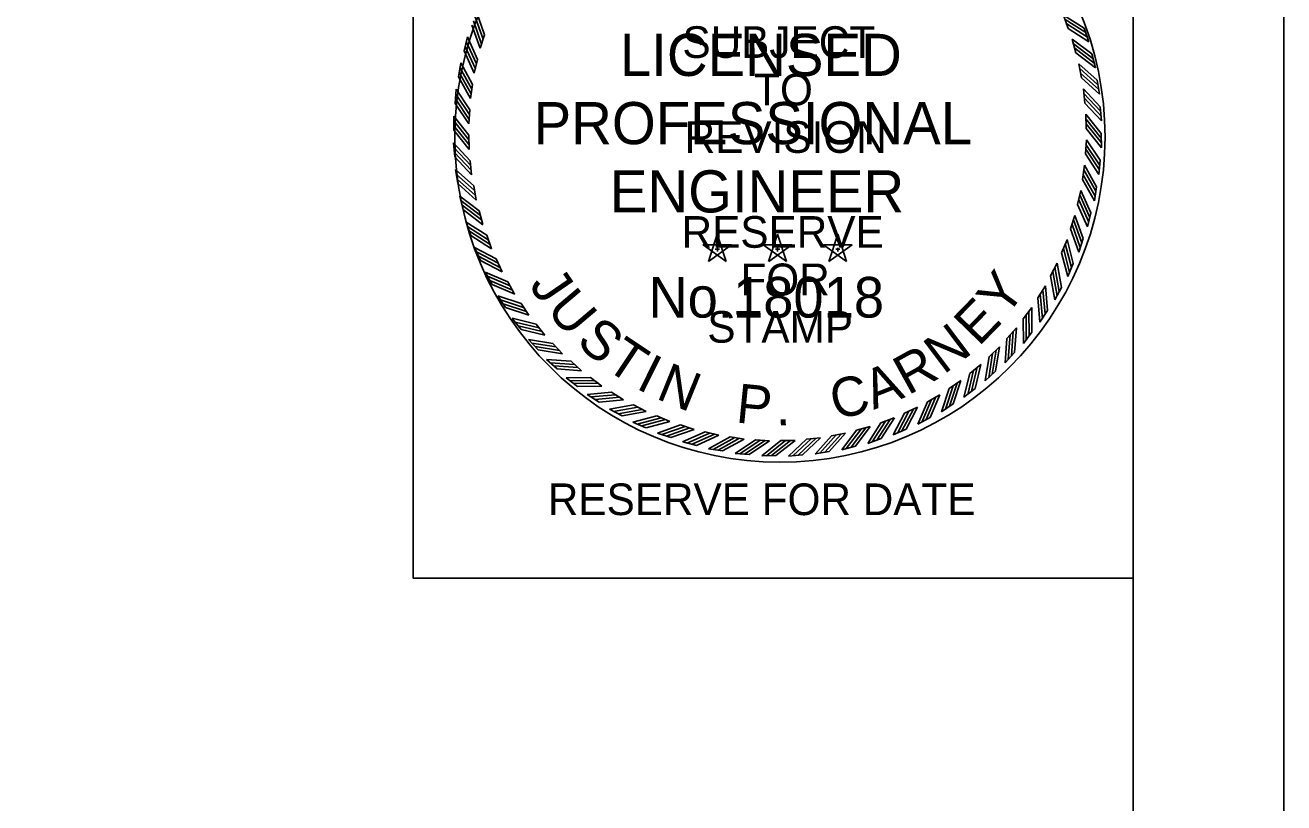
# Model space of a CAD drawing. Extents: x 0 to 1228743, y 0 to 152440.
# Drawn here: x 29.181 to 34, y 16.545 to 19.522 of the extents above; entities that cross this region are included whole.
import ezdxf

# ---------------------------------------------------------------- set-up
doc = ezdxf.new("R2010")
doc.units = 0
for name, color, linetype in [('R_Border', 7, 'Continuous'), ('R_Draft', 7, 'Continuous'), ('R_No Plot', 7, 'Continuous'), ('STAMP_JUSTIN', 7, 'Continuous')]:
    doc.layers.add(name, color=color, linetype=linetype)

msp = doc.modelspace()

# ---------------------------------------------------------------- linework, layer by layer
at = {"layer": 'R_Border'}
msp.add_line((33.4232, 0.5768), (33.4232, 21.4232), dxfattribs=at)
msp.add_lwpolyline([(34, 22), (0, 22), (0, 0), (34, 0)], close=True, dxfattribs=at)
at = {"layer": 'R_Draft'}
msp.add_circle((32.0709, 19.0937), 1.2447, dxfattribs=at)
at = {"layer": 'R_No Plot'}
for points in [[(33.4232, 17.4053), (33.4232, 10.8708), (1.516, 10.8708), (1.516, 21.4232), (27.1592, 21.4232), (27.1592, 20.4352), (28.7492, 20.4352), (30.6666, 20.4352)], [(30.6666, 20.4352), (30.6666, 17.4053), (33.4232, 17.4053)]]:
    msp.add_lwpolyline(points, dxfattribs=at)
at = {"layer": 'STAMP_JUSTIN'}
for p, q in [((33.1567, 19.5604), (33.1749, 19.5091)), ((30.8619, 19.4237), (30.8748, 19.4765)), ((30.9231, 19.4331), (30.9403, 19.4848)), ((33.1899, 19.4685), (33.2038, 19.4158)), ((33.236, 19.5098), (33.2541, 19.4586)), ((30.8404, 19.3236), (30.8488, 19.3773)), ((30.9006, 19.338), (30.9135, 19.3909)), ((33.2154, 19.3741), (33.2248, 19.3205)), ((33.2647, 19.4115), (33.2785, 19.3589)), ((30.8272, 19.222), (30.8312, 19.2762)), ((30.886, 19.2413), (30.8945, 19.2952)), ((33.233, 19.2779), (33.238, 19.2237)), ((33.2852, 19.3111), (33.2946, 19.2576)), ((30.8794, 19.1438), (30.8834, 19.1981)), ((33.2426, 19.1807), (33.2431, 19.1262)), ((33.2974, 19.2094), (33.3023, 19.1553)), ((30.8225, 19.1197), (30.822, 19.174)), ((30.881, 19.0461), (30.8805, 19.1005)), ((33.2441, 19.0829), (33.2401, 19.0286)), ((33.3011, 19.107), (33.3016, 19.0527)), ((30.8262, 19.0173), (30.8212, 19.0714)), ((30.8905, 18.9488), (30.8855, 19.003)), ((33.2375, 18.9854), (33.2291, 18.9316)), ((33.2963, 19.0047), (33.2923, 18.9505)), ((30.8383, 18.9156), (30.8289, 18.9691)), ((30.9081, 18.8526), (30.8987, 18.9063)), ((33.2831, 18.9032), (33.2747, 18.8495)), ((30.8588, 18.8153), (30.845, 18.8678)), ((33.2229, 18.8887), (33.2101, 18.8358)), ((30.9336, 18.7583), (30.9198, 18.8109)), ((33.2004, 18.7936), (33.1832, 18.7419)), ((33.2616, 18.803), (33.2487, 18.7502)), ((30.8875, 18.717), (30.8694, 18.7682)), ((30.9668, 18.6663), (30.9486, 18.7177)), ((31.8312, 18.7213), (31.7972, 18.6171)), ((31.865, 18.6171), (31.8312, 18.7215)), ((32.0617, 18.7213), (32.0277, 18.6171)), ((32.0955, 18.6171), (32.0617, 18.7215)), ((32.2921, 18.7213), (32.2581, 18.6171)), ((32.326, 18.6171), (32.2922, 18.7215)), ((33.1701, 18.7007), (33.1487, 18.6506)), ((33.2319, 18.705), (33.2147, 18.6534)), ((30.9243, 18.6213), (30.902, 18.6709)), ((31.886, 18.6815), (31.7763, 18.6816)), ((31.7764, 18.6815), (31.865, 18.617)), ((31.7973, 18.6171), (31.8861, 18.6815)), ((31.8234, 18.664), (31.8397, 18.664)), ((31.8313, 18.6699), (31.8313, 18.6561)), ((32.1165, 18.6815), (32.0068, 18.6816)), ((32.0069, 18.6815), (32.0955, 18.617)), ((32.0278, 18.6171), (32.1166, 18.6815)), ((32.0538, 18.664), (32.0701, 18.664)), ((32.0618, 18.6699), (32.0618, 18.6561)), ((32.3469, 18.6815), (32.2372, 18.6816)), ((32.2373, 18.6815), (32.326, 18.617)), ((32.2583, 18.6171), (32.3471, 18.6815)), ((32.2843, 18.664), (32.3006, 18.664)), ((32.2922, 18.6699), (32.2922, 18.6561)), ((31.0074, 18.5774), (30.9851, 18.6271)), ((33.1323, 18.6106), (33.1068, 18.5624)), ((33.1941, 18.6098), (33.1728, 18.5598)), ((30.9688, 18.5291), (30.9425, 18.5766)), ((31.0553, 18.4922), (31.0289, 18.5398)), ((33.0871, 18.5239), (33.0577, 18.478)), ((33.1487, 18.518), (33.1233, 18.4699)), ((31.0208, 18.4408), (30.9907, 18.486)), ((31.11, 18.4112), (31.0798, 18.4565)), ((33.0349, 18.4412), (33.0019, 18.3979)), ((33.0958, 18.4302), (33.0665, 18.3845)), ((31.0799, 18.3572), (31.0461, 18.3997)), ((31.1713, 18.335), (31.1374, 18.3777)), ((32.9761, 18.3631), (32.9396, 18.3227)), ((31.1457, 18.2787), (31.1085, 18.3183)), ((33.0359, 18.3472), (33.0029, 18.304)), ((31.2386, 18.2641), (31.2013, 18.3039)), ((32.911, 18.2902), (32.8713, 18.2529)), ((32.9693, 18.2694), (32.9328, 18.229)), ((31.2177, 18.2059), (31.1774, 18.2423)), ((31.3115, 18.1991), (31.2711, 18.2356)), ((32.8401, 18.2229), (32.7975, 18.189)), ((31.2956, 18.1393), (31.2524, 18.1722)), ((31.3896, 18.1402), (31.3463, 18.1733)), ((32.8965, 18.1973), (32.8568, 18.1601)), ((32.7639, 18.1616), (32.7186, 18.1314)), ((32.818, 18.1315), (32.7754, 18.0977)), ((31.3786, 18.0793), (31.3329, 18.1086)), ((31.4723, 18.088), (31.4264, 18.1174)), ((32.6829, 18.1069), (32.6353, 18.0806)), ((32.7343, 18.0724), (32.6891, 18.0423)), ((31.4664, 18.0264), (31.4183, 18.0519)), ((31.5589, 18.0429), (31.5108, 18.0683)), ((31.6491, 18.005), (31.599, 18.0264)), ((32.5977, 18.0591), (32.548, 18.0367)), ((31.5581, 17.981), (31.5082, 18.0024)), ((31.742, 17.9747), (31.6903, 17.9919)), ((32.4169, 17.9852), (32.3642, 17.9714)), ((32.5088, 18.0184), (32.4575, 18.0002)), ((32.5538, 17.9759), (32.5042, 17.9536)), ((32.646, 18.0204), (32.5985, 17.9941)), ((31.6534, 17.9433), (31.6018, 17.9604)), ((31.7514, 17.9135), (31.6986, 17.9264)), ((31.8371, 17.9522), (31.7842, 17.9651)), ((31.9338, 17.9376), (31.88, 17.9461)), ((32.0313, 17.931), (31.977, 17.935)), ((32.129, 17.9326), (32.0746, 17.9321)), ((32.2263, 17.9422), (32.1721, 17.9372)), ((32.3225, 17.9598), (32.2688, 17.9503)), ((32.4582, 17.9392), (32.4069, 17.921)), ((31.8515, 17.892), (31.7979, 17.9005)), ((31.9531, 17.8788), (31.8989, 17.8828)), ((32.1578, 17.8778), (32.1037, 17.8728)), ((32.2595, 17.8899), (32.206, 17.8805)), ((32.3599, 17.9104), (32.3073, 17.8966)), ((32.0554, 17.8741), (32.0011, 17.8736))]:
    msp.add_line(p, q, dxfattribs=at)
for points in [[(30.9402, 19.4848), (30.9088, 19.5734)], [(30.9231, 19.4331), (30.8917, 19.5217)], [(30.9288, 19.4496), (30.8974, 19.5382)], [(30.9344, 19.4676), (30.9029, 19.5562)], [(33.1567, 19.5605), (33.2359, 19.5098)], [(33.1623, 19.5439), (33.2416, 19.4933)], [(33.169, 19.5263), (33.2483, 19.4756)], [(30.9134, 19.3909), (30.8748, 19.4766)], [(33.1749, 19.5091), (33.2541, 19.4585)], [(33.1898, 19.4685), (33.2646, 19.4115)], [(30.9006, 19.3379), (30.862, 19.4236)], [(30.9049, 19.3549), (30.8663, 19.4406)], [(30.909, 19.3733), (30.8703, 19.459)], [(33.1941, 19.4516), (33.2689, 19.3946)], [(33.1993, 19.4334), (33.2741, 19.3764)], [(30.8944, 19.2951), (30.8488, 19.3773)], [(33.2038, 19.4159), (33.2786, 19.3589)], [(33.2153, 19.3742), (33.2851, 19.3112)], [(30.886, 19.2413), (30.8404, 19.3235)], [(30.8889, 19.2585), (30.8433, 19.3408)], [(30.8914, 19.2772), (30.8458, 19.3595)], [(33.2182, 19.3569), (33.288, 19.2939)], [(33.2219, 19.3384), (33.2917, 19.2754)], [(30.8834, 19.1981), (30.8312, 19.2763)], [(33.2249, 19.3205), (33.2947, 19.2576)], [(33.2329, 19.278), (33.2973, 19.2095)], [(30.8809, 19.1612), (30.8287, 19.2394)], [(30.8819, 19.18), (30.8297, 19.2582)], [(33.2344, 19.2606), (33.2987, 19.1921)], [(33.2365, 19.2418), (33.3009, 19.1733)], [(30.8795, 19.1437), (30.8273, 19.2219)], [(33.238, 19.2238), (33.3024, 19.1553)], [(33.2425, 19.1807), (33.301, 19.1071)], [(30.8804, 19.1005), (30.8219, 19.1741)], [(30.8804, 19.0824), (30.8219, 19.156)], [(30.881, 19.0635), (30.8225, 19.1371)], [(33.2425, 19.1632), (33.301, 19.0896)], [(33.2431, 19.1444), (33.3016, 19.0708)], [(30.881, 19.046), (30.8225, 19.1196)], [(33.2431, 19.1263), (33.3016, 19.0527)], [(33.244, 19.083), (33.2963, 19.0048)], [(30.8855, 19.003), (30.8211, 19.0715)], [(30.887, 18.9849), (30.8226, 19.0534)], [(30.8892, 18.9662), (30.8248, 19.0347)], [(33.2416, 19.0467), (33.2938, 18.9685)], [(33.2426, 19.0656), (33.2948, 18.9874)], [(30.8906, 18.9487), (30.8262, 19.0173)], [(33.2375, 18.9855), (33.2831, 18.9032)], [(33.2401, 19.0287), (33.2924, 18.9505)], [(30.8986, 18.9062), (30.8288, 18.9692)], [(30.9016, 18.8884), (30.8318, 18.9513)], [(33.2321, 18.9495), (33.2777, 18.8673)], [(33.2346, 18.9682), (33.2802, 18.886)], [(30.9053, 18.8698), (30.8355, 18.9328)], [(30.9082, 18.8526), (30.8384, 18.9156)], [(33.2291, 18.9316), (33.2747, 18.8494)], [(30.9197, 18.8109), (30.8449, 18.8679)], [(30.9242, 18.7933), (30.8494, 18.8503)], [(33.2146, 18.8534), (33.2532, 18.7677)], [(33.2186, 18.8719), (33.2573, 18.7861)], [(33.2229, 18.8888), (33.2616, 18.8031)], [(30.9294, 18.7752), (30.8546, 18.8322)], [(30.9337, 18.7582), (30.8589, 18.8152)], [(33.2004, 18.7937), (33.2318, 18.7051)], [(33.2101, 18.8359), (33.2488, 18.7502)], [(30.9486, 18.7176), (30.8694, 18.7682)], [(30.9545, 18.7005), (30.8753, 18.7511)], [(33.1892, 18.7591), (33.2206, 18.6705)], [(33.1947, 18.7771), (33.2262, 18.6885)], [(30.9612, 18.6828), (30.8819, 18.7334)], [(30.9669, 18.6663), (30.8876, 18.7169)], [(33.1701, 18.7008), (33.1941, 18.6098)], [(33.1833, 18.742), (33.2147, 18.6534)], [(30.9851, 18.627), (30.902, 18.6709)], [(30.9924, 18.6104), (30.9092, 18.6544)], [(33.1488, 18.6506), (33.1728, 18.5597)], [(33.156, 18.6672), (33.1801, 18.5763)], [(33.1631, 18.6847), (33.1871, 18.5938)], [(31.0005, 18.5934), (30.9173, 18.6373)], [(31.0075, 18.5774), (30.9244, 18.6213)], [(33.1323, 18.6106), (33.1487, 18.5181)], [(31.0289, 18.5398), (30.9425, 18.5767)], [(31.0376, 18.5239), (30.9511, 18.5607)], [(33.1069, 18.5625), (33.1233, 18.4699)], [(33.1155, 18.5784), (33.1319, 18.4858)], [(33.1239, 18.5953), (33.1403, 18.5027)], [(31.0471, 18.5075), (30.9606, 18.5444)], [(31.0554, 18.4922), (30.9689, 18.529)], [(33.0775, 18.5093), (33.0862, 18.4157)], [(33.0871, 18.524), (33.0958, 18.4303)], [(31.0798, 18.4564), (30.9906, 18.4861)], [(31.0897, 18.4413), (31.0005, 18.4709)], [(31.1005, 18.4258), (31.0113, 18.4554)], [(33.0578, 18.478), (33.0665, 18.3844)], [(33.0677, 18.4932), (33.0764, 18.3996)], [(31.1101, 18.4112), (31.0209, 18.4408)], [(33.013, 18.4122), (33.014, 18.3182)], [(33.0242, 18.4275), (33.0251, 18.3335)], [(33.0349, 18.4413), (33.0359, 18.3473)], [(31.1374, 18.3776), (31.0461, 18.3998)], [(31.1486, 18.3633), (31.0572, 18.3855)], [(31.1606, 18.3488), (31.0692, 18.3709)], [(32.9761, 18.3632), (32.9693, 18.2695)], [(33.0019, 18.398), (33.0029, 18.3039)], [(31.1714, 18.335), (31.08, 18.3571)], [(31.2013, 18.3038), (31.1085, 18.3183)], [(32.9396, 18.3228), (32.9328, 18.229)], [(32.9519, 18.3361), (32.9451, 18.2423)], [(32.9642, 18.3504), (32.9574, 18.2566)], [(31.2136, 18.2905), (31.1207, 18.305)], [(31.2268, 18.277), (31.1339, 18.2915)], [(31.2387, 18.2641), (31.1458, 18.2786)], [(32.8847, 18.2652), (32.8701, 18.1723)], [(32.8981, 18.2784), (32.8836, 18.1855)], [(32.911, 18.2903), (32.8965, 18.1974)], [(31.2711, 18.2355), (31.1774, 18.2423)], [(31.2845, 18.2232), (31.1907, 18.23)], [(31.2987, 18.2109), (31.205, 18.2177)], [(32.8401, 18.223), (32.818, 18.1316)], [(32.8713, 18.253), (32.8568, 18.1601)], [(31.3116, 18.199), (31.2178, 18.2059)], [(31.3463, 18.1732), (31.2523, 18.1722)], [(32.7975, 18.189), (32.7754, 18.0977)], [(32.8118, 18.2002), (32.7897, 18.1088)], [(32.8263, 18.2122), (32.8042, 18.1208)], [(31.3606, 18.1621), (31.2666, 18.1611)], [(31.3759, 18.151), (31.2819, 18.15)], [(31.3897, 18.1402), (31.2957, 18.1393)], [(32.7187, 18.1314), (32.6891, 18.0422)], [(32.7338, 18.1413), (32.7042, 18.0521)], [(32.7493, 18.1522), (32.7197, 18.0629)], [(32.764, 18.1617), (32.7343, 18.0725)], [(31.4264, 18.1173), (31.3328, 18.1086)], [(31.4416, 18.1074), (31.348, 18.0987)], [(31.4577, 18.0976), (31.3641, 18.0889)], [(31.4723, 18.088), (31.3787, 18.0793)], [(32.6354, 18.0806), (32.5985, 17.9941)], [(32.6513, 18.0892), (32.6144, 18.0027)], [(32.6676, 18.0987), (32.6307, 18.0122)], [(32.683, 18.107), (32.6461, 18.0205)], [(31.5108, 18.0683), (31.4183, 18.0519)], [(31.5268, 18.0597), (31.4342, 18.0432)], [(31.5436, 18.0512), (31.4511, 18.0348)], [(31.559, 18.0429), (31.4664, 18.0265)], [(31.599, 18.0264), (31.5081, 18.0023)], [(32.5481, 18.0367), (32.5042, 17.9536)], [(32.5647, 18.044), (32.5208, 17.9608)], [(32.5817, 18.0521), (32.5378, 17.969)], [(32.5977, 18.0591), (32.5538, 17.976)], [(31.6156, 18.0191), (31.5247, 17.9951)], [(31.6331, 18.012), (31.5422, 17.988)], [(31.6491, 18.005), (31.5582, 17.981)], [(31.6904, 17.9919), (31.6018, 17.9604)], [(31.7075, 17.986), (31.6189, 17.9545)], [(31.7255, 17.9804), (31.6369, 17.949)], [(31.7421, 17.9747), (31.6535, 17.9433)], [(32.3818, 17.9758), (32.3248, 17.901)], [(32.4, 17.981), (32.343, 17.9062)], [(32.4169, 17.9853), (32.3599, 17.9105)], [(32.4575, 18.0002), (32.4069, 17.921)], [(32.4747, 18.0061), (32.424, 17.9269)], [(32.4923, 18.0128), (32.4417, 17.9336)], [(32.5089, 18.0185), (32.4582, 17.9392)], [(31.7843, 17.965), (31.6985, 17.9264)], [(31.8018, 17.9606), (31.7161, 17.9219)], [(31.8202, 17.9565), (31.7345, 17.9179)], [(31.8372, 17.9522), (31.7515, 17.9136)], [(31.88, 17.946), (31.7978, 17.9004)], [(31.8979, 17.943), (31.8157, 17.8975)], [(31.9166, 17.9405), (31.8344, 17.8949)], [(31.9339, 17.9376), (31.8516, 17.892)], [(31.9771, 17.935), (31.8989, 17.8828)], [(31.9951, 17.9335), (31.9169, 17.8813)], [(32.0139, 17.9325), (31.9358, 17.8803)], [(32.0314, 17.9311), (31.9532, 17.8789)], [(32.0747, 17.932), (32.001, 17.8735)], [(32.0928, 17.932), (32.0191, 17.8735)], [(32.1116, 17.9326), (32.038, 17.8741)], [(32.1291, 17.9326), (32.0555, 17.8741)], [(32.1722, 17.9371), (32.1036, 17.8727)], [(32.1902, 17.9386), (32.1217, 17.8742)], [(32.209, 17.9408), (32.1404, 17.8764)], [(32.2264, 17.9422), (32.1579, 17.8778)], [(32.2689, 17.9503), (32.2059, 17.8804)], [(32.2868, 17.9532), (32.2238, 17.8834)], [(32.3053, 17.9569), (32.2423, 17.8871)], [(32.3225, 17.9598), (32.2596, 17.89)], [(32.3643, 17.9713), (32.3073, 17.8966)]]:
    msp.add_lwpolyline(points, dxfattribs=at)

# ---------------------------------------------------------------- texts
at = {"layer": 'R_Draft'}
for s, height, p in [('SUBJECT', 0.1211, (31.6976, 19.3964)), ('TO', 0.1211, (31.9722, 19.2148)), ('REVISION', 0.1211, (31.7062, 19.0331)), ('RESERVE', 0.1211, (31.6943, 18.6698)), ('FOR', 0.1211, (31.9198, 18.4882)), ('STAMP', 0.1211, (31.7929, 18.3065)), ('RESERVE FOR DATE', 0.121097, (31.1822, 17.6466))]:
    msp.add_text(s, height=height, dxfattribs=at).set_placement(p)
at = {"layer": 'STAMP_JUSTIN'}
for s, height, p in [('LICENSED', 0.16134, (31.4583, 19.3274)), ('PROFESSIONAL', 0.161342, (31.1279, 19.0662)), ('ENGINEER', 0.16134, (31.4198, 18.8049)), ('No.18018', 0.15558, (31.5673, 18.4026))]:
    msp.add_text(s, height=height, dxfattribs=at).set_placement(p)
for s, rotation, p in [('J', 304.3679, (31.1079, 18.5265)), ('Y', 53.4433, (32.935, 18.3984)), ('U', 310.2047, (31.1725, 18.432)), ('E', 45.7825, (32.8319, 18.2891)), ('S', 318.9599, (31.2866, 18.3038)), ('N', 37.0272, (32.6976, 18.1823)), ('T', 326.256, (31.3957, 18.2113)), ('R', 29.0016, (32.5614, 18.1034)), ('I', 333.552, (31.5157, 18.1333)), ('N', 337.9296, (31.5921, 18.0941)), ('A', 21.7056, (32.4292, 18.0488)), ('C', 14.0448, (32.2841, 18.01)), ('P', 354.3456, (31.8995, 18.0014)), ('.', 2.3712, (32.0563, 17.9889))]:
    msp.add_text(s, height=0.1501, rotation=rotation, dxfattribs=at).set_placement(p)

doc.saveas('drawing.dxf')
